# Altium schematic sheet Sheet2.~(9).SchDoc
size A; SheetNumber: 1; SheetTotal: 1
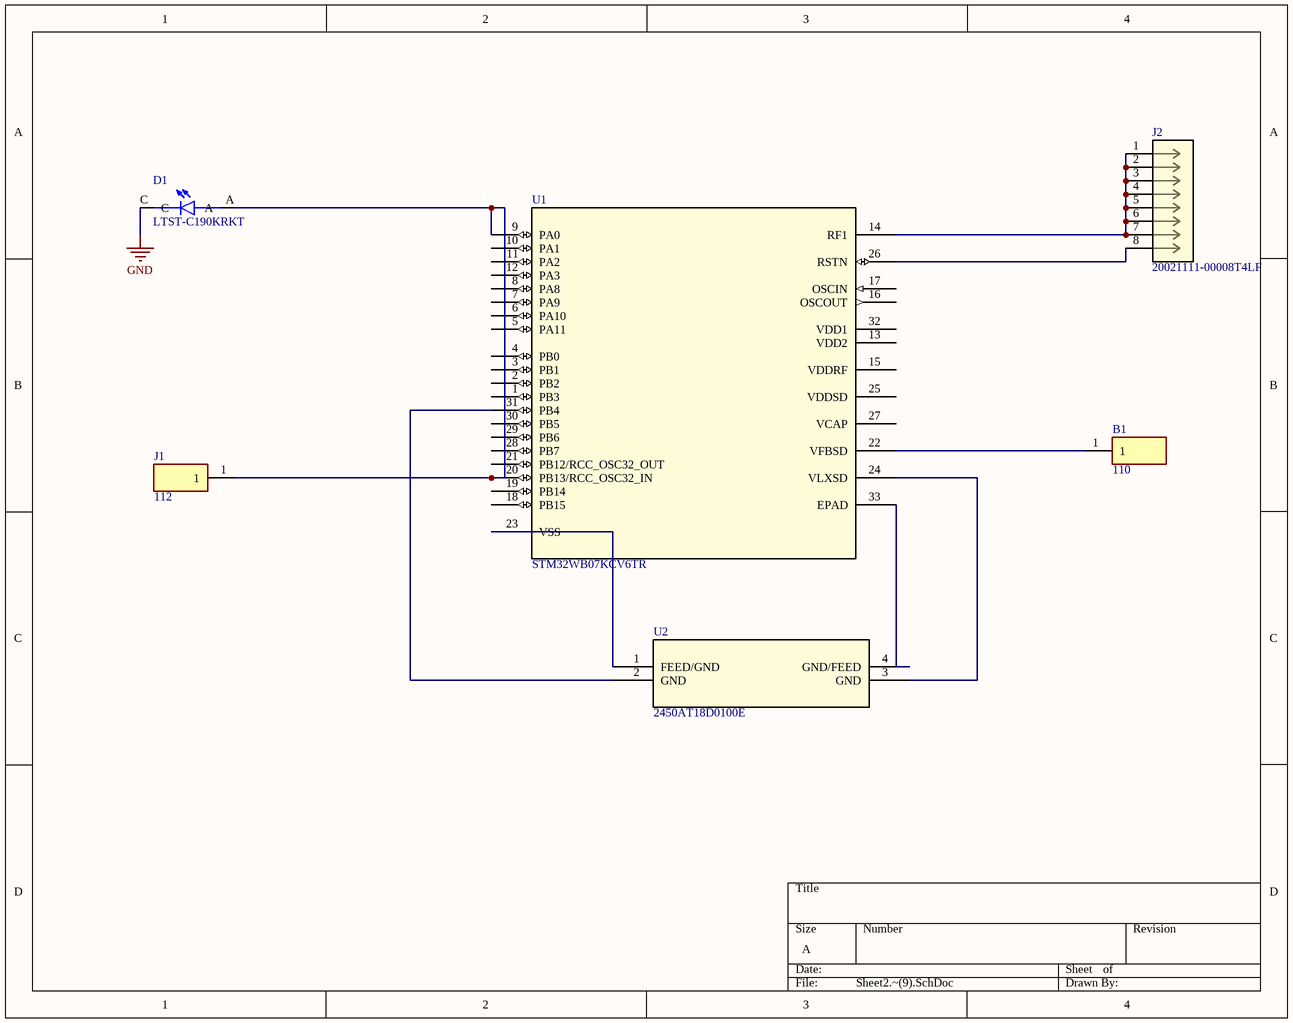
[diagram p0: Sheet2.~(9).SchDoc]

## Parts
B1  110  [110]
D1  LTST-C190KRKT  [LEDC1608X35N]
J1  112  [112]
J2  20021111-00008T4LF  [CONN_20021111-00008T4LF_AMP]
U1  STM32WB07KCV6TR  [VFQFPN-32_STM]
U2  2450AT18D0100E  [2450AT18D0100E_JOT]

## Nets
GND: D1.C
NetB1_1: B1.1 U1.22(VFBSD)
NetD1_A: D1.A J1.1 U1.9(PA0) U1.20(PB13/RCC_OSC32_IN)
NetJ2_1: J2.1 J2.2 J2.3 J2.4 J2.5 J2.6 J2.7 U1.14(RF1)
NetJ2_8: J2.8 U1.26(RSTN)
NetU1_23: U1.23(VSS) U2.1(FEED/GND)
NetU1_24: U1.24(VLXSD) U2.3(GND)
NetU1_31: U1.31(PB4) U2.2(GND)
NetU1_33: U1.33(EPAD) U2.4(GND/FEED)

Not connected (* = marked no-connect by the designer): U1 1(PB3) 2(PB2) 3(PB1) 4(PB0) 5(PA11) 6(PA10) 7(PA9) 8(PA8) 10(PA1) 11(PA2) 12(PA3) 13(VDD2) 15(VDDRF) 16(OSCOUT) 17(OSCIN) 18(PB15) 19(PB14) 21(PB12/RCC_OSC32_OUT) 25(VDDSD) 27(VCAP) 28(PB7) 29(PB6) 30(PB5) 32(VDD1)

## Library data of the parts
B1 = 110: Battery Contacts S/M COIN CELL CNCT POSITIVE 16mm UP; Manufacturer_Name: Keystone Electronics; Geometry.Height: 3.3mm
D1 = LTST-C190KRKT: Red 631nm LED Indication - Discrete 2V 0603 (1608 Metric); MF: Lite-On Inc.
J1 = 112: Battery Contacts S/M COIN CELL CNCT NEGATIVE 16mm UP; Manufacturer_Name: Keystone Electronics; Geometry.Height: 3mm
J2 = 20021111-00008T4LF: No Description Available; Mfr_Name: Amphenol ICC
U1 = STM32WB07KCV6TR: Ultra-low-power, Arm Cortex-M0+ MCU 64 MHz with 256 Kbytes of Flash memory, 64 Kbytes of RAM,  Bluetooth LE 5.4; Manufacturer_Name: STMicroelectronics
U2 = 2450AT18D0100E: No Description Available; Manufacturer_Name: Johanson Technology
